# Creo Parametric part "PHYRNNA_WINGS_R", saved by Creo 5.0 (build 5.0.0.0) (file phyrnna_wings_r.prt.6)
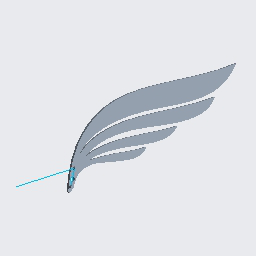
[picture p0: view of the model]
Units: Inch lbm Second (Pro/E Default); INCH, POUND, SECS

Created from: INLBS_PART_SOLID.PRT

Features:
  1. datum plane "RIGHT"
  2. datum plane "TOP"
  3. datum plane "FRONT"
  4. coordinate system
  5. sketch "Sketch 1"
  6. sketch "Sketch 2"
  7. extrusion "Extrude 1"
  8. sketch "Sketch 4"
  9. sketch "Sketch 3"
  10. extrusion "Extrude 2"

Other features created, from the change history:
  group "COPIED_GROUP" (4 times)
  sketch "Sketch 1" (4 times)
  sketch "Sketch 2" (4 times)
  mirror "Mirror 1" (2 times)
  sketch "Sketch 1 (2)" (2 times)
  sketch "Sketch 2 (2)"
  sketch "REFERENCE" (2 times)

Other named items: WING_S, REFERENCE_1, WING_E, PEG_S, PEG_E, REFERENCE_2

Surfaces: 8 tabulated cylinder, 3 plane, 3 cylinder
